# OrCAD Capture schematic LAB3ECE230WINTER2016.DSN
size A
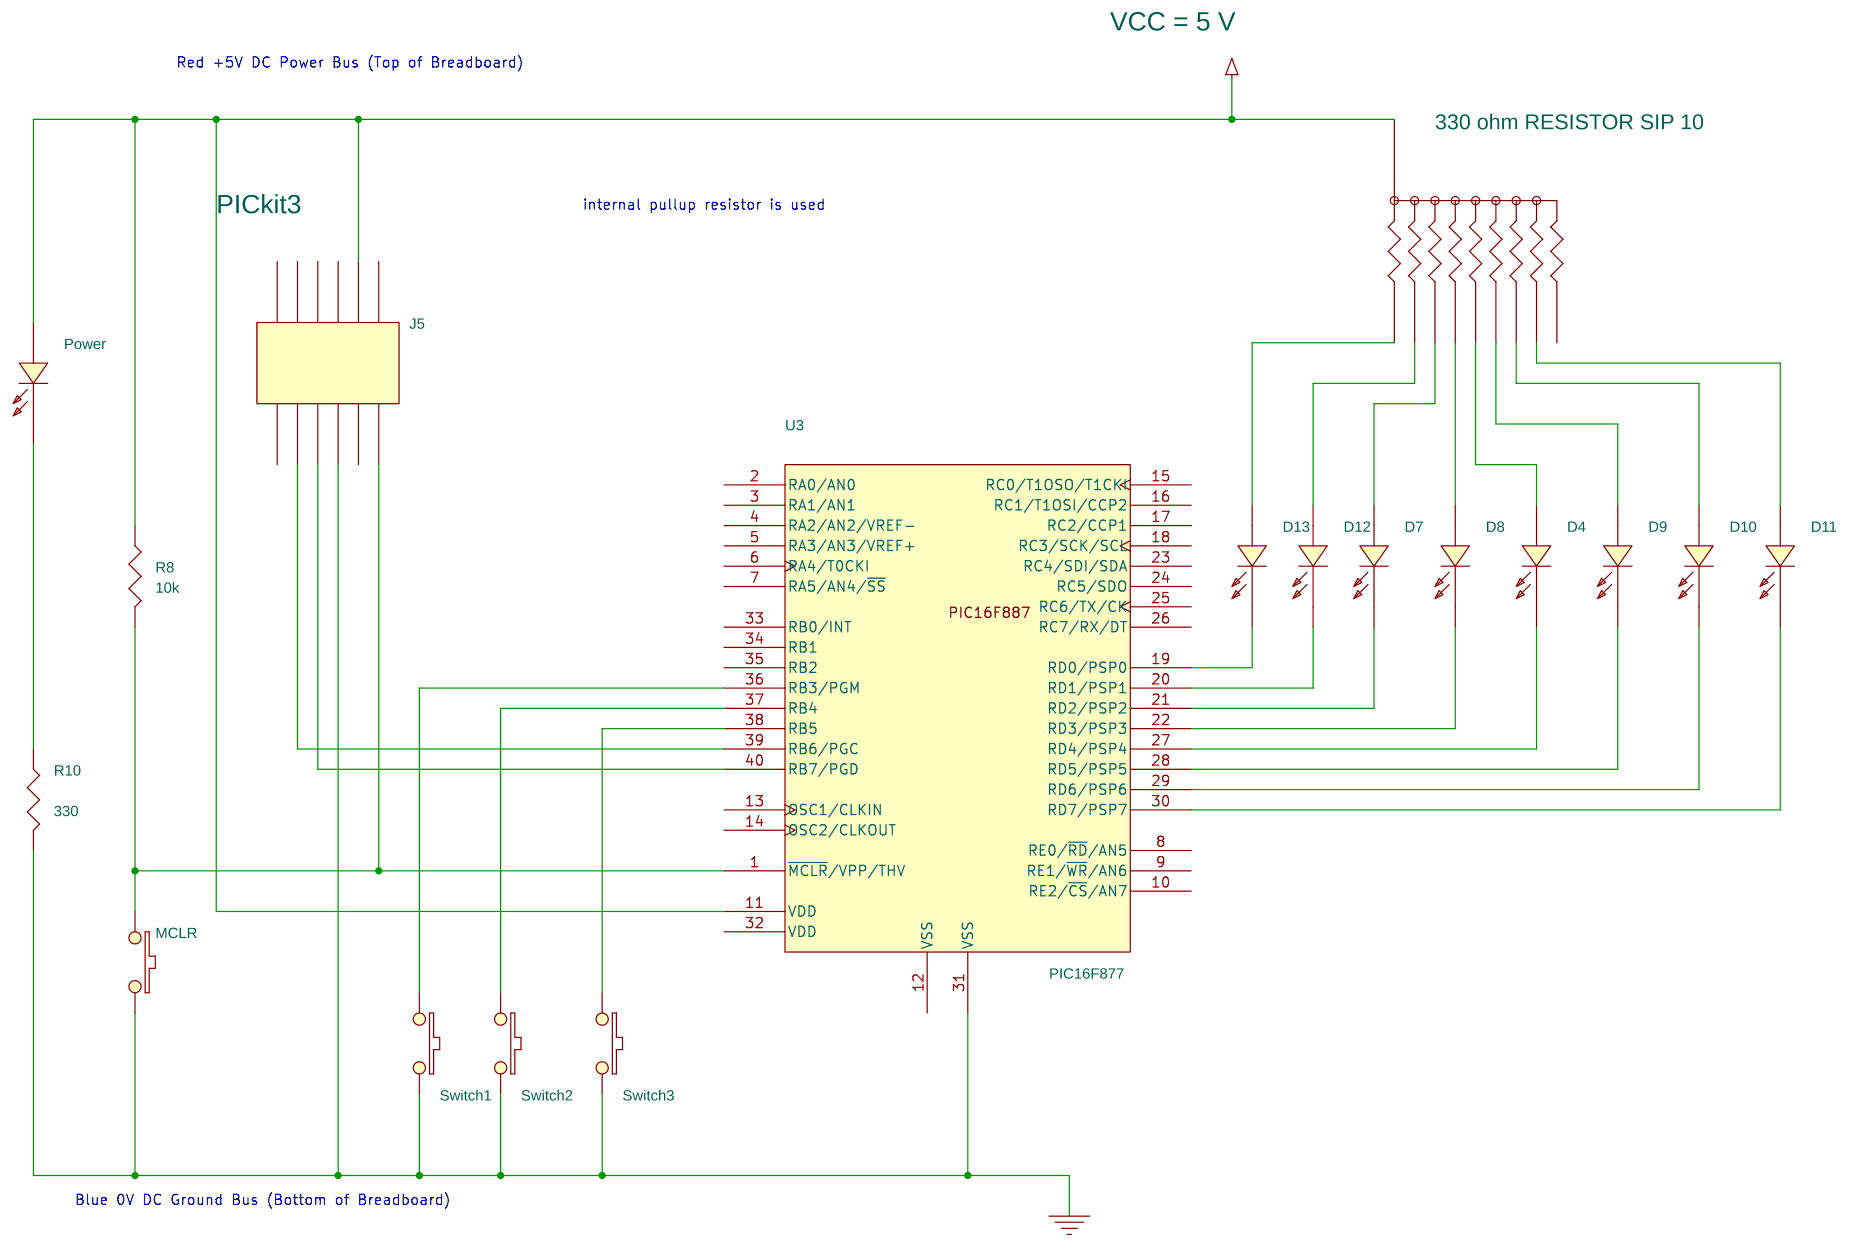
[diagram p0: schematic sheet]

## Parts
D4  Interrupt LED
D7  Interrupt LED
D8  Interrupt LED
D9  Interrupt LED
D10  Interrupt LED
D11  Interrupt LED
D12  Interrupt LED
D13  Interrupt LED
J5  PICkit3
MCLR  SW PUSHBUTTON
Power  5VDC
R8  10k
R10  330
R11  330 ohm RESISTOR SIP 10
Switch1  SW PUSHBUTTON
Switch2  SW PUSHBUTTON
Switch3  SW PUSHBUTTON
U3  PIC16F877

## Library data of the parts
D4 D7-D13 Power = LED
J5 = CONNECTOR_EDGE_6x2_0
MCLR Switch1-Switch3 = SW_PUSHBUTTON
R8 R10 = RESISTOR
R11 = RESISTOR_SIP_10
U3 = PIC16F877_3

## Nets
GND: J5.3 MCLR.2 R10.2 Switch1.2 Switch2.2 Switch3.2 U3.31(VSS)
Vcc = 5 V: J5.2 Power.1(ANODE) R8.1 R11.1 U3.11(VDD)
VDD: U3.32(VDD)
N1028634: D7.2(CATHODE) U3.21(RD2/PSP2)
N1028652: D8.2(CATHODE) U3.22(RD3/PSP3)
N1028656: D9.2(CATHODE) U3.28(RD5/PSP5)
N1028688: D11.2(CATHODE) U3.30(RD7/PSP7)
N1028720: D12.2(CATHODE) U3.20(RD1/PSP1)
N1028738: D13.2(CATHODE) U3.19(RD0/PSP0)
N1028772: D4.2(CATHODE) U3.27(RD4/PSP4)
N1028780: D10.2(CATHODE) U3.29(RD6/PSP6)
N1028796: D13.1(ANODE) R11.2
N1028800: D12.1(ANODE) R11.3
N1028846: D7.1(ANODE) R11.4
N1028858: D8.1(ANODE) R11.5
N1028862: D4.1(ANODE) R11.6
N1028874: D9.1(ANODE) R11.7
N1028886: D10.1(ANODE) R11.8
N1028898: D11.1(ANODE) R11.9
N1028964: Switch3.1 U3.38(RB5)
N1028972: Switch2.1 U3.37(RB4)
N1028980: Switch1.1 U3.36(RB3/PGM)
N1028988: J5.1 MCLR.1 R8.2 U3.1(~{MCLR}/VPP/THV)
N1029010: Power.2(CATHODE) R10.1
N1029130: J5.5 U3.39(RB6/PGC)
N1029150: J5.4 U3.40(RB7/PGD)

Not connected (* = marked no-connect by the designer): J5 6; R11 10; U3 2(RA0/AN0) 3(RA1/AN1) 4(RA2/AN2/VREF-) 5(RA3/AN3/VREF+) 6(RA4/T0CKI) 7(RA5/AN4/~{SS}) 8(RE0/~{RD}/AN5) 9(RE1/~{WR}/AN6) 10(RE2/~{CS}/AN7) 12(VSS) 13(OSC1/CLKIN) 14(OSC2/CLKOUT) 15(RC0/T1OSO/T1CKI) 16(RC1/T1OSI/CCP2) 17(RC2/CCP1) 18(RC3/SCK/SCL) 23(RC4/SDI/SDA) 24(RC5/SDO) 25(RC6/TX/CK) 26(RC7/RX/DT) 33(RB0/INT) 34(RB1) 35(RB2)

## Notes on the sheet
- Red +5V DC Power Bus (Top of Breadboard)
- internal pullup resistor is used
- Blue 0V DC Ground Bus (Bottom of Breadboard)
